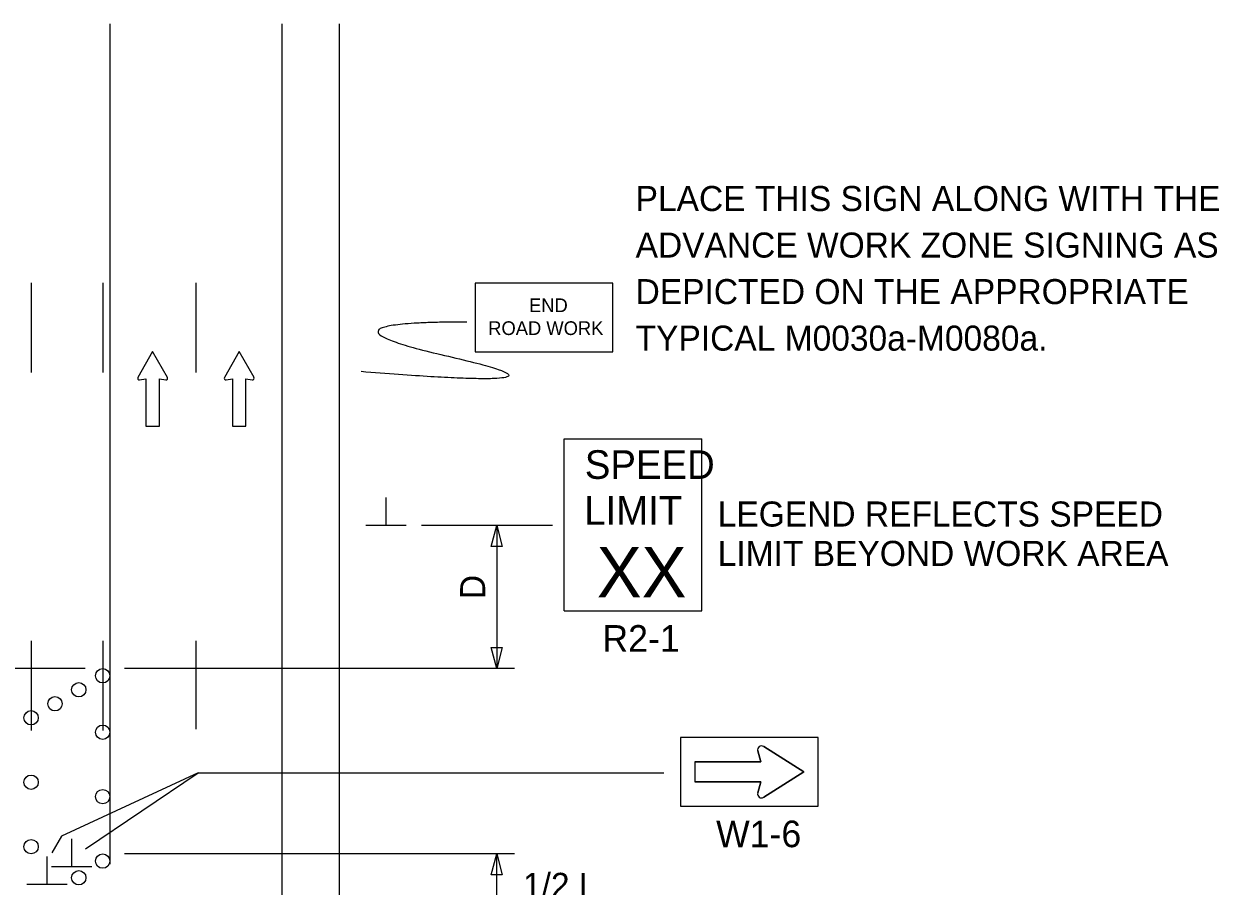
# Model space of a CAD drawing. Extents: x 16525 to 18478, y 5730 to 6927.
# Drawn here: x 17075.6 to 17409.3, y 6676.7 to 6917.6 of the extents above; entities that cross this region are included whole.
import ezdxf

# ---------------------------------------------------------------- set-up
doc = ezdxf.new("R2010")
doc.units = 0
for name, color, linetype in [('ALI_LEGAL_EX', 7, 'Continuous'), ('MT_SCRATCH_LEVEL_E', 7, 'Continuous'), ('PAVT_EDGE_EX', 7, 'Continuous'), ('TRAFFIC_SIGNS_PR', 7, 'Continuous'), ('TYPICAL_TEXT_DIMEN_PR', 7, 'Continuous')]:
    doc.layers.add(name, color=color, linetype=linetype)

msp = doc.modelspace()

# ---------------------------------------------------------------- linework, layer by layer
at = {"layer": 'ALI_LEGAL_EX'}
for points in [[(17077.59, 6845.22), (17077.59, 6820.22)], [(17097.59, 6845.22), (17097.59, 6820.22)], [(17123.59, 6845.22), (17123.59, 6820.22)], [(17077.59, 6745.22), (17077.59, 6720.22)], [(17097.59, 6745.22), (17097.59, 6720.22)], [(17123.59, 6745.22), (17123.59, 6720.56)]]:
    msp.add_lwpolyline(points, dxfattribs=at)
at = {"layer": 'MT_SCRATCH_LEVEL_E'}
for p, q in [((17111.52, 6826.05), (17107.41, 6818.81)), ((17111.52, 6826.05), (17107.41, 6818.81)), ((17115.67, 6818.81), (17111.52, 6826.05)), ((17115.67, 6818.81), (17111.52, 6826.05)), ((17135.69, 6826.05), (17131.58, 6818.81)), ((17135.69, 6826.05), (17131.58, 6818.81)), ((17139.84, 6818.81), (17135.69, 6826.05)), ((17139.84, 6818.81), (17135.69, 6826.05)), ((17107.89, 6818.12), (17109.67, 6818.44)), ((17107.89, 6818.12), (17109.67, 6818.44)), ((17109.67, 6818.44), (17109.67, 6805.18)), ((17109.67, 6818.44), (17109.67, 6805.18)), ((17113.41, 6805.18), (17113.41, 6818.44)), ((17113.41, 6818.44), (17115.19, 6818.12)), ((17113.41, 6805.18), (17113.41, 6818.44)), ((17113.41, 6818.44), (17115.19, 6818.12)), ((17132.06, 6818.12), (17133.84, 6818.44)), ((17132.06, 6818.12), (17133.84, 6818.44)), ((17133.84, 6818.44), (17133.84, 6805.18)), ((17133.84, 6818.44), (17133.84, 6805.18)), ((17137.58, 6805.18), (17137.58, 6818.44)), ((17137.58, 6818.44), (17139.36, 6818.12)), ((17137.58, 6805.18), (17137.58, 6818.44)), ((17137.58, 6818.44), (17139.36, 6818.12)), ((17109.67, 6805.18), (17113.41, 6805.18)), ((17109.67, 6805.18), (17113.41, 6805.18)), ((17133.84, 6805.18), (17137.58, 6805.18)), ((17133.84, 6805.18), (17137.58, 6805.18))]:
    msp.add_line(p, q, dxfattribs=at)
for centre, start, end in [((17107.82, 6818.58), 150.4248, 279.9638), ((17107.82, 6818.58), 150.4248, 279.9638), ((17115.26, 6818.58), 260.0362, 29.7731), ((17115.26, 6818.58), 260.0362, 29.7731), ((17131.99, 6818.58), 150.4248, 279.9638), ((17131.99, 6818.58), 150.4248, 279.9638), ((17139.43, 6818.58), 260.0362, 29.7731), ((17139.43, 6818.58), 260.0362, 29.7731)]:
    msp.add_arc(centre, 0.463, start, end, dxfattribs=at)
at = {"layer": 'PAVT_EDGE_EX'}
for p, q in [((17099.59, 6917.57), (17099.59, 6682.86)), ((17147.59, 6917.57), (17147.59, 6063.18)), ((17163.59, 6917.57), (17163.59, 6063.18))]:
    msp.add_line(p, q, dxfattribs=at)
at = {"layer": 'TRAFFIC_SIGNS_PR'}
for p, q in [((17226.43, 6801.61), (17264.83, 6801.61)), ((17226.43, 6753.61), (17226.43, 6801.61)), ((17264.83, 6753.61), (17264.83, 6801.61)), ((17226.43, 6753.61), (17264.83, 6753.61)), ((17281.31, 6711.41), (17280.47, 6714.47)), ((17282.15, 6715.71), (17293.31, 6708.61)), ((17262.91, 6711.41), (17281.31, 6711.41)), ((17262.91, 6711.41), (17262.91, 6705.81)), ((17293.31, 6708.61), (17282.15, 6701.51)), ((17281.31, 6705.81), (17262.91, 6705.81)), ((17280.47, 6702.75), (17281.31, 6705.81))]:
    msp.add_line(p, q, dxfattribs=at)
for points in [[(17201.62, 6825.92), (17240.02, 6825.92), (17240.02, 6845.12), (17201.62, 6845.12)], [(17258.91, 6699.01), (17297.31, 6699.01), (17297.31, 6718.21), (17258.91, 6718.21)]]:
    msp.add_lwpolyline(points, close=True, dxfattribs=at)
for points in [[(17280.47, 6714.47), (17281.31, 6711.41), (17262.91, 6711.41), (17262.91, 6705.81), (17281.31, 6705.81), (17280.47, 6702.75)], [(17282.15, 6701.51), (17293.31, 6708.61), (17282.15, 6715.71)]]:
    msp.add_lwpolyline(points, dxfattribs=at)
for centre in [(17097.59, 6735.47), (17090.92, 6731.56), (17084.26, 6727.64), (17077.59, 6723.72), (17097.59, 6719.69), (17077.59, 6705.72), (17097.59, 6701.69), (17077.59, 6687.72), (17097.59, 6683.69), (17090.92, 6679.03)]:
    msp.add_circle(centre, 2, dxfattribs=at)
for centre, start, end in [((17281.55, 6714.76), 57.5304, 195.3269), ((17281.55, 6714.76), 57.5304, 195.3269), ((17281.55, 6702.45), 164.6731, 302.4696), ((17281.55, 6702.45), 164.6731, 302.4696)]:
    msp.add_arc(centre, 1.12, start, end, dxfattribs=at)
msp.add_open_spline([(17199.27, 6834.28), (17152.03, 6834.28), (17237.05, 6814.94), (17169.72, 6820.43)], degree=2, dxfattribs=at)
at = {"layer": 'TYPICAL_TEXT_DIMEN_PR'}
for p, q in [((17176.71, 6777.47), (17176.71, 6785.26)), ((17182.34, 6777.47), (17171.09, 6777.47)), ((17223.13, 6777.47), (17186.59, 6777.47)), ((17206.02, 6771.61), (17207.59, 6777.47)), ((17207.59, 6777.47), (17209.16, 6771.61)), ((17207.59, 6777.47), (17207.59, 6737.47)), ((17207.59, 6771.61), (17206.02, 6771.61)), ((17209.16, 6771.61), (17207.59, 6771.61)), ((17207.59, 6737.47), (17206.02, 6743.34)), ((17206.02, 6743.34), (17207.59, 6743.34)), ((17207.59, 6737.47), (17206.02, 6743.34)), ((17206.02, 6743.34), (17207.59, 6743.34)), ((17207.59, 6743.34), (17209.16, 6743.34)), ((17209.16, 6743.34), (17207.59, 6737.47)), ((17207.59, 6743.34), (17209.16, 6743.34)), ((17209.16, 6743.34), (17207.59, 6737.47)), ((17092.68, 6737.47), (16962.49, 6737.47)), ((17212.59, 6737.47), (17103.65, 6737.47)), ((17124.22, 6708.37), (17086.08, 6690.64)), ((17092.76, 6687.09), (17124.22, 6708.37)), ((17124.22, 6708.37), (17254.22, 6708.37)), ((17086.08, 6690.64), (17083.35, 6686)), ((17088.96, 6682.12), (17088.96, 6689.91)), ((17082.04, 6677.17), (17082.04, 6684.95)), ((17212.59, 6685.69), (17103.65, 6685.69)), ((17206.02, 6679.82), (17207.59, 6685.69)), ((17207.59, 6669.72), (17207.59, 6685.69)), ((17207.59, 6685.69), (17209.16, 6679.82)), ((17094.59, 6682.12), (17083.34, 6682.12)), ((17207.59, 6679.82), (17206.02, 6679.82)), ((17209.16, 6679.82), (17207.59, 6679.82)), ((17087.66, 6677.17), (17076.41, 6677.17))]:
    msp.add_line(p, q, dxfattribs=at)

# ---------------------------------------------------------------- texts
at = {"layer": 'TRAFFIC_SIGNS_PR'}
for s, height, p in [('PLACE THIS SIGN ALONG WITH THE', 7, (17246.38, 6865.29)), ('ADVANCE WORK ZONE SIGNING AS', 7, (17246.38, 6852.29)), ('DEPICTED ON THE APPROPRIATE', 7, (17246.38, 6839.29)), ('END', 3.831, (17216.62, 6837.05)), ('ROAD WORK', 3.831, (17205.23, 6830.66)), ('TYPICAL M0030a-M0080a.', 7, (17246.38, 6826.29)), ('SPEED', 8, (17232.2, 6790.47)), ('LIMIT', 8, (17232.04, 6777.67)), ('XX', 14.031, (17235.55, 6757.36)), ('R2-1', 7.44, (17237.11, 6742.17)), ('W1-6', 7.44, (17268.85, 6687.57))]:
    msp.add_text(s, height=height, dxfattribs=at).set_placement(p)
at = {"layer": 'TYPICAL_TEXT_DIMEN_PR'}
for s, p in [('LEGEND REFLECTS SPEED', (17269.3, 6777.15)), ('LIMIT BEYOND WORK AREA', (17269.3, 6766.15)), ('1/2 L', (17214.94, 6673.41))]:
    msp.add_text(s, height=7, dxfattribs=at).set_placement(p)
msp.add_text('D', height=7, rotation=90, dxfattribs=at).set_placement((17204.39, 6756.88))

doc.saveas('drawing.dxf')
